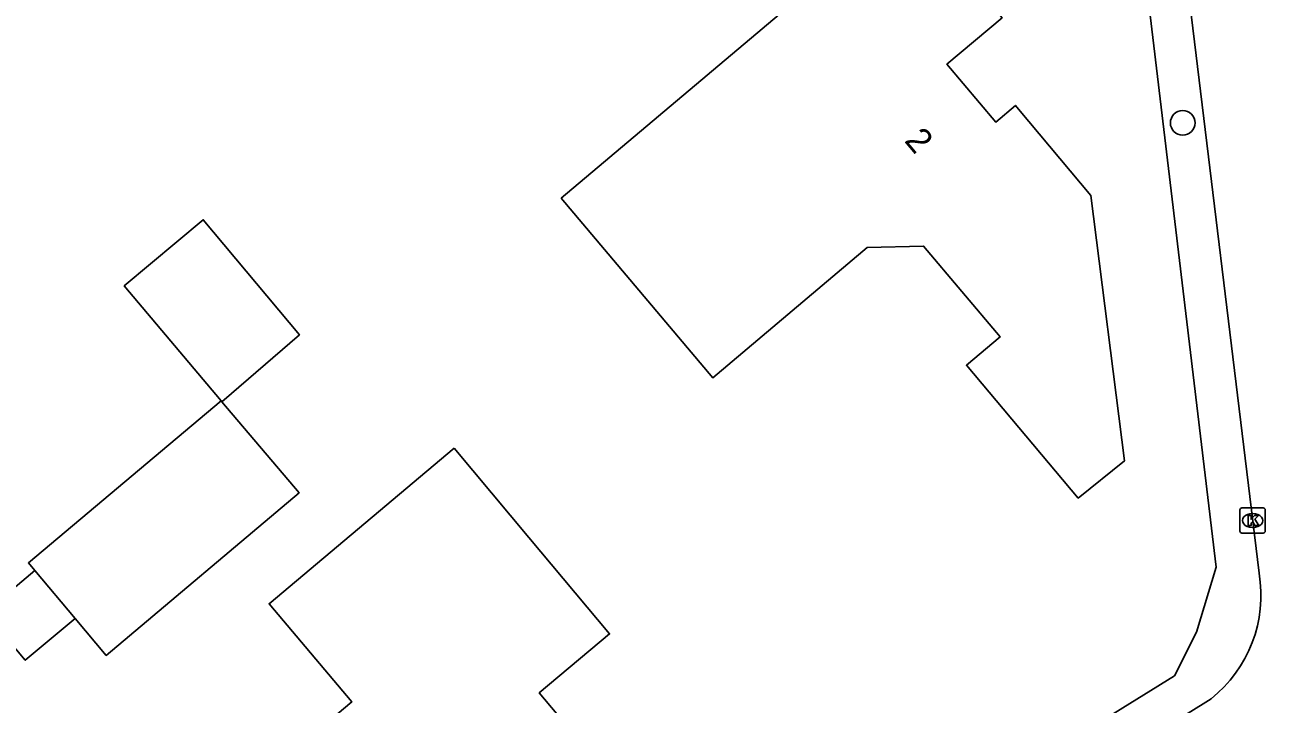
# Model space of a CAD drawing. Extents: x 157321 to 158827, y 386650 to 388532.
# Drawn here: x 157866.23 to 157915.48, y 387262.54 to 387289.52 of the extents above; entities that cross this region are included whole.
import ezdxf

# ---------------------------------------------------------------- set-up
doc = ezdxf.new("R2010")
doc.units = 0
for name, color, linetype in [('IMGEO_Boom', 7, 'Continuous'), ('IMGEO_Groenvoorziening', 7, 'Continuous'), ('IMGEO_Kolk', 7, 'Continuous'), ('IMGEO_Pand', 7, 'Continuous'), ('IMGEO_Pand_nummerreeks', 7, 'Continuous'), ('IMGEO_Rijbaan_lokaal_gesloten', 7, 'Continuous')]:
    doc.layers.add(name, color=color, linetype=linetype)

msp = doc.modelspace()

# ---------------------------------------------------------------- linework, layer by layer
at = {"layer": 'IMGEO_Boom'}
msp.add_circle((157912.201, 387285.626), 0.489, dxfattribs=at)
at = {"layer": 'IMGEO_Groenvoorziening'}
msp.add_lwpolyline([(157900.068, 387256.707), (157900.267, 387256.855), (157900.468, 387256.598), (157911.871, 387263.665), (157912.743, 387265.397), (157913.526, 387267.973), (157910.585, 387292.678)], dxfattribs=at)
at = {"layer": 'IMGEO_Kolk'}
for p, q in [((157914.475, 387269.406), (157914.475, 387270.258)), ((157914.55, 387270.332), (157915.402, 387270.332)), ((157914.963, 387270.112), (157914.988, 387270.112)), ((157915.476, 387270.258), (157915.476, 387269.406)), ((157914.986, 387269.552), (157914.961, 387269.552)), ((157915.402, 387269.332), (157914.55, 387269.332))]:
    msp.add_line(p, q, dxfattribs=at)
for points in [[(157914.475, 387269.406), (157914.475, 387270.258)], [(157914.55, 387270.332), (157915.402, 387270.332)], [(157914.796, 387270.032), (157914.919, 387270.032), (157914.919, 387269.881), (157915.049, 387270.032), (157915.213, 387270.032), (157915.067, 387269.881), (157915.22, 387269.632), (157915.068, 387269.632), (157914.983, 387269.796), (157914.919, 387269.729), (157914.919, 387269.632), (157914.796, 387269.632), (157914.796, 387270.032)], [(157915.476, 387270.258), (157915.476, 387269.406)], [(157915.402, 387269.332), (157914.55, 387269.332)]]:
    msp.add_lwpolyline(points, dxfattribs=at)
for centre, start, end in [((157914.552, 387270.256), 91.552, 178.448), ((157914.552, 387270.256), 91.552, 178.448), ((157915.4, 387270.256), 1.552, 88.448), ((157915.4, 387270.256), 1.552, 88.448), ((157914.552, 387269.408), 181.552, 268.448), ((157914.552, 387269.408), 181.552, 268.448), ((157915.4, 387269.408), 271.552, 358.448), ((157915.4, 387269.408), 271.552, 358.448)]:
    msp.add_arc(centre, 0.0765, start, end, dxfattribs=at)
for centre, major_axis, ratio, start_param, end_param in [((157914.962, 387269.832), (-0.387, 0.002), 0.722429, 4.712389, 7.853982), ((157914.987, 387269.832), (-0.39, 0.002), 0.717154, 1.570796, 4.712389)]:
    msp.add_ellipse(centre, major_axis=major_axis, ratio=ratio, start_param=start_param, end_param=end_param, dxfattribs=at)
at = {"layer": 'IMGEO_Pand'}
for points in [[(157887.521, 387282.636), (157901.297, 387294.261), (157905.033, 387289.804), (157902.839, 387287.956), (157904.777, 387285.655), (157905.562, 387286.316), (157905.682, 387286.172), (157908.556, 387282.737), (157909.884, 387272.196), (157908.055, 387270.725), (157903.611, 387275.999), (157904.949, 387277.127), (157901.914, 387280.729), (157899.674, 387280.672), (157893.54, 387275.503), (157887.521, 387282.636)], [(157874.054, 387274.547), (157877.134, 387277.208), (157873.314, 387281.776), (157870.177, 387279.152), (157874.02, 387274.587)], [(157866.626, 387267.843), (157866.37, 387268.147), (157874.02, 387274.587)], [(157874.054, 387274.547), (157877.121, 387270.935), (157869.462, 387264.475), (157868.223, 387265.946)], [(157874.02, 387274.587), (157874.054, 387274.547)], [(157883.277, 387272.701), (157886.239, 387269.161), (157889.448, 387265.326), (157886.654, 387262.986), (157889.173, 387259.978), (157886.171, 387257.432), (157888.535, 387254.644), (157883.029, 387250), (157881.196, 387248.454), (157879.896, 387250), (157877.978, 387252.28), (157875.012, 387255.808), (157876.992, 387257.473), (157875.374, 387259.398), (157879.209, 387262.624), (157875.93, 387266.523), (157883.277, 387272.701)], [(157868.223, 387265.946), (157866.245, 387264.281), (157864.648, 387266.178), (157866.626, 387267.843)], [(157868.223, 387265.946), (157866.626, 387267.843)]]:
    msp.add_lwpolyline(points, dxfattribs=at)
at = {"layer": 'IMGEO_Rijbaan_lokaal_gesloten'}
for points in [[(157912.185, 387292.883), (157915.233, 387267.735)], [(157913.327, 387262.75), (157901.077, 387255.115)]]:
    msp.add_lwpolyline(points, dxfattribs=at)
msp.add_arc((157910.059, 387266.856), 5.248, 308.5113, 9.6403, dxfattribs=at)

# ---------------------------------------------------------------- texts
at = {"layer": 'IMGEO_Pand_nummerreeks'}
msp.add_text('2', height=1, rotation=310.1055, dxfattribs=at).set_placement((157901.121, 387284.904))

doc.saveas('drawing.dxf')
